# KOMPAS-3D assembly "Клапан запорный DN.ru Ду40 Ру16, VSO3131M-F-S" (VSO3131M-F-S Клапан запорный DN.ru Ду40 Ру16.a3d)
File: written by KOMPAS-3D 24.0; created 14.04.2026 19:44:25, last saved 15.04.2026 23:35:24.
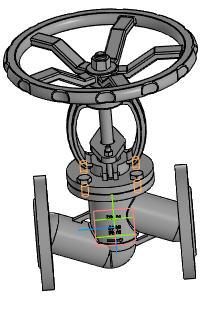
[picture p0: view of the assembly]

Document properties: Автор: R2D2; Полное имя файла: E:\Работа\Зайцев\VSO3131M-F-S Клапан запорный DN.ru Ду15-100 Ру16\DN40\исходные материалы\VSO3131M-F-S Клапан запорный DN.ru Ду40 Ру16.a3d

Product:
- Component [detail]: Корпус  | qty 1  | pos. 1  | Масса: 6.9; Автор: R2D2; source file: Корпус.m3d
- Component [detail]: Клапан запорный DN.ru Ду40 Ру16  | designation VSO1121M-F-S  | qty 1  | pos. 2  | Масса: 9.32; Раздел спецификации: Прочие изделия; Примечание: D090-01946; Автор: R2D2; source file: 2.m3d
- Component [standard]: Hexagon head screw ISO 4017 - М10 x 20  | qty 4  | Масса: 0.023019; Раздел спецификации: Стандартные изделия; Рассекать на разрезах: no
- Part/product: Клапан запорный DN.ru Ду40 Ру16  | designation VSO3131M-F-S
    Масса: 8.25
    Раздел спецификации: Прочие изделия
    Примечание: D090-02950

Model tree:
1. Массив по концентрической сетке:1  (with: Грань.Элемент вращения:2, Грань.Операция без истории:1)  (labels: Грань.Элемент выдавливания:9.Экземпляр ( 1, 2 ))  (4 pattern instances)
     Шаг 2 = 360; Расстояние = -250

Expressions: D090-01946
Referenced files in E:\Работа\Зайцев\VSO3131M-F-S Клапан запорный DN.ru Ду15-100 Ру16\DN40\исходные материалы\: Корпус.m3d, 2.m3d
Referenced files in C:\Program Files\ASCON\KOMPAS-3D v24\Libs\PolynomLib\DATA\vault\Methods\Kompas\3D\: PLib_Bolt_1_ISO_1100.m3d
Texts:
  VSO1121M-F-S
  Hexagon head screw
  BOSimple***PART:c031cb5e-65ec-2f83-1ced-75228c8ad34f***PART:A259_7B16EF33AB1642D2[16;1,5;20;10;-;Undefined]
  Программные изделия  и базы данных
  VSO3131M-F-S
  VSO1121M-F-S Клапан запорный DN.ru Ду40 Ру16
  Hexagon head screw ISO 4017 - М10 x 20 (1)
  hole1
  hole2
  Hexagon head screw ISO 4017 - М10 x 20 (2)
  Hexagon head screw ISO 4017 - М10 x 20 (3)
  Hexagon head screw ISO 4017 - М10 x 20 (4)
  Ось Y.Начало координат
  Плоскость XY.Начало координат
  Плоскость ZX.Начало координат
